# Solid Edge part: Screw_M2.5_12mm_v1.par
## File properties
Author: Houman
Template: Normal.par
Last saved by: Houman
Revision: 11
Application: Solid Edge
Density: 7750.000 kg/m^3
Accuracy: 0.990
Material: Stainless steel
Face Style: Steel
Fill Style: ANSI32(Steel)
Virtual Style: Stainless steel
Coef. of Thermal Exp: 1.6e-05
Thermal Conductivity: 17.0
Specific Heat: 502.0
Modulus of Elasticity: 193053196000.0
Poission's Ratio: 0.29
Yield Stress: 310264065.0
Ultimate Stress: 641212401.0
Elongation: 0.0
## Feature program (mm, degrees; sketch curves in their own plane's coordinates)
body "unnamed Body 1"
sketch for "unnamed Cutout 1" plane through (0, 0, -14.5) normal (0, 0, -1) x-axis (1, 0, 0)
extrude "unnamed Cutout 1" cut finite 0.1 along -normal
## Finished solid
Body 1: solid body, 26 faces, 43 edges, 20 vertices.
  Faces by surface: plane 11, cone 9, cylinder 4, spline 2
  Edges by curve: circle 17, line 12, intersection 10, spline 4
Bounding box of the edges (mm; curved faces can reach further): 4.500 x 4.500 x 14.500, from (-2.25, -2.25, -14.5) to (2.25, 2.25, 0).
Cylindrical faces by radius (mm): R0.125 x1, R0.9577 x1, R1.25 x1, R2.25 x1
Conical faces (half-angle, radius in mm at the cone's reference point): 45 deg R1.1547 x6, 45 deg R2.025 x1, 45 deg R2.25 x1, 55 deg R0.7037 x1
Planar faces by outward normal: +x 1, +z 2, -x 1, -z 3, oblique 4
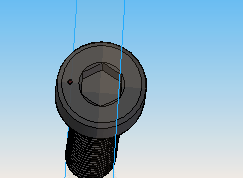
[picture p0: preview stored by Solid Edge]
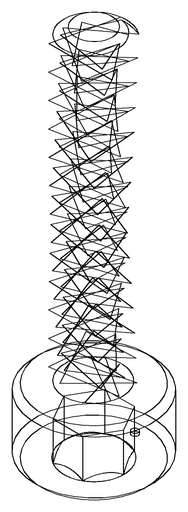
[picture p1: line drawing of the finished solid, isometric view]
